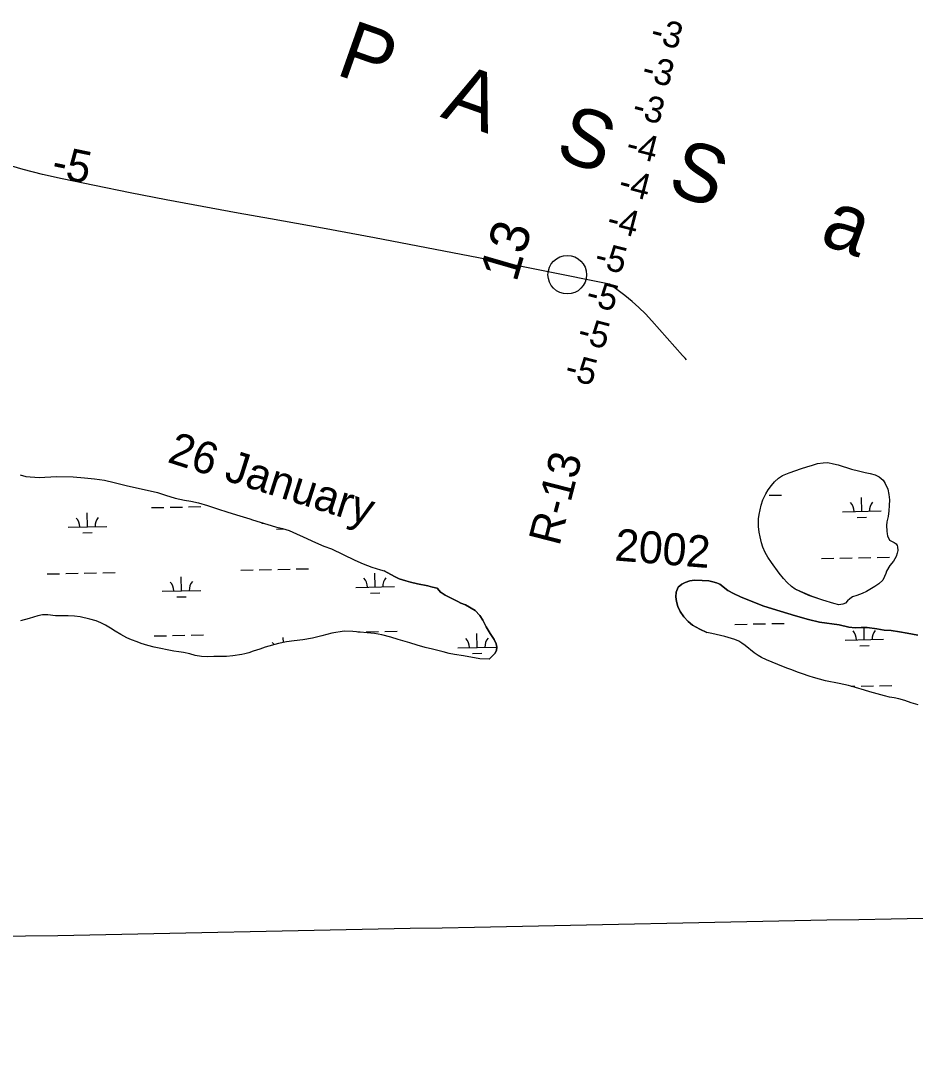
# Model space of a CAD drawing. Extents: x 3989314 to 4027622, y 243956 to 270014.
# Drawn here: x 4009687 to 4012006, y 255456 to 258147 of the extents above; entities that cross this region are included whole.
import ezdxf

# ---------------------------------------------------------------- set-up
doc = ezdxf.new("R2010")
doc.units = 0
for name, color, linetype in [('V-GRID-MAJR', 7, 'Continuous'), ('V-RIVR-EDGE', 7, 'Continuous'), ('V-RIVR-IDEN', 7, 'Continuous'), ('V-RIVR-MILE', 7, 'Continuous'), ('V-RIVR-RANG', 7, 'Continuous'), ('V-RIVR-RANG-IDEN', 7, 'Continuous'), ('V-TOPO-MINR', 7, 'Continuous'), ('V-TOPO-MINR-IDEN', 7, 'Continuous'), ('V-WETL-SWMP', 7, 'Continuous')]:
    doc.layers.add(name, color=color, linetype=linetype)

msp = doc.modelspace()

# ---------------------------------------------------------------- linework, layer by layer
at = {"layer": 'V-GRID-MAJR'}
msp.add_spline([(3993497.6, 255455.7), (3998815.3, 255559.8), (4004133, 255664.6), (4009450.7, 255770.2), (4014768.4, 255876.5), (4020086, 255983.7), (4025403.7, 256091.6)], degree=3, dxfattribs=at)
at = {"layer": 'V-RIVR-EDGE'}
for points in [[(4011730.5, 256658), (4011694.9, 256674.5), (4011685.5, 256680.7), (4011674.4, 256691.6), (4011664.7, 256702), (4011653, 256715.7), (4011633.4, 256743.1), (4011623.8, 256757.3), (4011617.3, 256769), (4011611.3, 256782.7), (4011607.4, 256794), (4011603.9, 256810), (4011601.6, 256821.8), (4011599.8, 256836.8), (4011599.9, 256856.5), (4011601.4, 256868), (4011606.3, 256892.2), (4011611, 256905.6), (4011618.6, 256921), (4011625.2, 256931.6), (4011633.3, 256942.7), (4011641.1, 256952.1), (4011651.5, 256961.5), (4011662.1, 256969.2), (4011679.4, 256975.7), (4011711.6, 256987), (4011725.1, 256991.5), (4011739.9, 256995.6), (4011752.6, 256999.5), (4011767.4, 257001.7), (4011779.9, 257002.1), (4011794.4, 256999.4), (4011805.9, 256996.1), (4011840.6, 256985.2), (4011858.8, 256980.5), (4011876.5, 256976.3), (4011889.1, 256973.7), (4011902.6, 256970.2), (4011912.4, 256965.5), (4011922.9, 256956.3), (4011928.1, 256948.2), (4011934.7, 256933.7), (4011938.1, 256919.4), (4011939.3, 256905.9), (4011938.7, 256890.9), (4011937.9, 256876.8), (4011936, 256862.5), (4011932.4, 256849.1), (4011931.4, 256839.1), (4011932.2, 256824.4), (4011933.4, 256817.4), (4011934.4, 256812.8), (4011939.7, 256801.3), (4011951.9, 256795.2), (4011956.4, 256791.6), (4011959.3, 256787.4), (4011959.8, 256784), (4011960.7, 256774.6), (4011959.7, 256767.5), (4011956.5, 256758.4), (4011950, 256746.6), (4011940.1, 256735.1), (4011931.8, 256720.4), (4011929.8, 256714.5), (4011926.6, 256706.6), (4011921.8, 256697.9), (4011911.4, 256688.1), (4011901.3, 256681.4), (4011879.4, 256668), (4011868.7, 256662.9), (4011855, 256657.9), (4011843.8, 256654.2), (4011836.9, 256649), (4011830.9, 256643.8), (4011825, 256638.2), (4011818.8, 256635.5), (4011808, 256633.8), (4011795.1, 256636.8), (4011767, 256645.7), (4011730.5, 256658)], [(4009685.5, 256970.4), (4009700.4, 256966.3), (4009734.9, 256963.5), (4009780.2, 256966.6), (4009823.2, 256965.5), (4009852.6, 256963), (4009878.7, 256960.4), (4009904.2, 256956.3), (4009929.4, 256950.8), (4009960.4, 256942.7), (4010042.1, 256924.3), (4010062.8, 256918), (4010087.2, 256910.1), (4010111.5, 256904.8), (4010128.1, 256902.5), (4010148.1, 256897.8), (4010171.3, 256890.7), (4010199.8, 256881.2), (4010221.9, 256874.6), (4010246.8, 256866.6), (4010280.9, 256856.6), (4010288.3, 256853.9), (4010327.9, 256841.5), (4010347.3, 256835.7), (4010365.8, 256831.3), (4010383.4, 256826), (4010402.5, 256818), (4010419.2, 256809.6), (4010451.7, 256794.7), (4010472.7, 256785.9), (4010492.8, 256778.6), (4010553, 256749.2), (4010575, 256740.1), (4010597.7, 256731.6), (4010620, 256724.4), (4010629.5, 256722)], [(4010766.6, 256677.1), (4010755.1, 256679.4), (4010742.2, 256682.4), (4010715.5, 256688.1), (4010697.5, 256692.7), (4010685.4, 256696), (4010668, 256701.3), (4010656, 256706.6), (4010629.5, 256722)], [(4011433.9, 256697.2), (4011421.5, 256695.7), (4011409.6, 256691.3), (4011400.7, 256687.3), (4011391.7, 256679), (4011386.4, 256666.8), (4011385.5, 256654.3), (4011387, 256642.1), (4011390.6, 256629.2), (4011397, 256616.5), (4011406.2, 256602.3), (4011417.5, 256590.4), (4011429, 256580.8), (4011447.6, 256570.7), (4011465.7, 256562.1)], [(4012012.7, 256555.3), (4011985.2, 256560.4), (4011965.5, 256563.8), (4011944.1, 256566.6), (4011926, 256567.8), (4011906.2, 256570.9), (4011881.9, 256574.5), (4011865.9, 256574.4), (4011850.4, 256573.6), (4011833.8, 256575.3), (4011808.6, 256581.5), (4011757.5, 256588.7), (4011729.6, 256595.5), (4011695.8, 256604.8), (4011636.3, 256623.1), (4011611.4, 256631.3), (4011553, 256654.1), (4011534.6, 256662.8), (4011520.5, 256670.5), (4011499.9, 256686.7), (4011491.3, 256690.6), (4011481.2, 256693.5), (4011470.7, 256695.5), (4011454, 256696.9), (4011433.9, 256697.2)], [(4010820.1, 256642.1), (4010798.1, 256653.1), (4010787.5, 256658.5), (4010777.3, 256665.2), (4010776.7, 256665.9), (4010766.6, 256677.1)], [(4010901.9, 256492.8), (4010917.1, 256508), (4010920.5, 256516.4), (4010921.3, 256524.2), (4010919.3, 256532.4), (4010914.2, 256543.5), (4010904.5, 256558.9), (4010894, 256576.5), (4010885.3, 256593.9), (4010877.4, 256605.8), (4010865.6, 256618.5), (4010840.1, 256633.7), (4010828.5, 256638.2), (4010820.1, 256642.1)], [(4010901.9, 256492.8), (4010877.4, 256493.8), (4010835.3, 256501.7), (4010811.4, 256504.9), (4010798.2, 256507.7), (4010782, 256511.9), (4010755.1, 256518.4), (4010735.6, 256522.9), (4010714.5, 256529.1), (4010695.9, 256534.9), (4010665.9, 256543.7), (4010646.3, 256549.9), (4010623.6, 256556), (4010604.4, 256559.5), (4010547.9, 256564.6), (4010525.3, 256565.7), (4010493.5, 256559.8), (4010467.8, 256552.8), (4010443.6, 256547.5), (4010418.1, 256543), (4010396, 256540.6), (4010376.6, 256537.9), (4010355.2, 256533.3), (4010321.3, 256523.4), (4010306.8, 256518.2), (4010290.2, 256513.1), (4010278.2, 256509.1), (4010268.5, 256506.4), (4010260.8, 256505), (4010237.2, 256501), (4010220.6, 256499.5), (4010204.5, 256499.4), (4010187.8, 256499.6), (4010171.5, 256499.1), (4010156, 256499.3), (4010139.5, 256502.4), (4010125.9, 256506.1), (4010109.1, 256510.1), (4010096.8, 256511.9), (4010084.2, 256513.3), (4010032.8, 256524.2), (4010016.4, 256528), (4009999.6, 256533.3), (4009988.7, 256537.2), (4009974.1, 256542.9), (4009961.9, 256548.3), (4009947, 256556.4), (4009931.7, 256565.4), (4009920, 256572.7), (4009907, 256580.5), (4009894.9, 256586.9), (4009882.6, 256591.9), (4009866.6, 256596.8), (4009841.5, 256602.5), (4009826.3, 256604.4), (4009810.1, 256604.7), (4009794.4, 256604.7), (4009777.6, 256605.1), (4009757.3, 256607.2), (4009743.4, 256607.5), (4009731.2, 256604.9), (4009708.7, 256597.8), (4009686.2, 256592.1)], [(4011607.6, 256496.9), (4011599, 256502.1), (4011588.3, 256509.3), (4011564.9, 256528.5), (4011557, 256534.4), (4011548.9, 256539.4), (4011538.8, 256543.4), (4011512.3, 256551.8), (4011478.9, 256558.9), (4011465.7, 256562.1)], [(4012013.3, 256374.2), (4011995.7, 256379.8), (4011978.8, 256385.5), (4011963.7, 256389.7), (4011951.8, 256392.3), (4011939.5, 256394.3), (4011926.2, 256397.7), (4011888.4, 256408), (4011874.8, 256412.2), (4011851.4, 256419.2), (4011833.2, 256424.1), (4011808.7, 256429.6), (4011773.9, 256436.6), (4011758.3, 256440.7), (4011742.7, 256445.3), (4011731, 256449), (4011713.8, 256455), (4011700.8, 256459.2), (4011685.8, 256464.7), (4011673.3, 256469.7), (4011649.6, 256478.7), (4011620.3, 256490.6), (4011607.6, 256496.9)]]:
    msp.add_lwpolyline(points, dxfattribs=at)
at = {"layer": 'V-RIVR-MILE'}
msp.add_circle((4011104, 257489.3), 50, dxfattribs=at)
at = {"layer": 'V-TOPO-MINR'}
msp.add_lwpolyline([(4011412.9, 257268.8), (4011409.7, 257272.6), (4011406.4, 257276.4), (4011403.1, 257280.2), (4011323.4, 257370.1), (4011307, 257387.5), (4011289.9, 257404.2), (4011271.9, 257420), (4011253.3, 257435), (4011215.5, 257463.7), (4011215.3, 257463.8), (4011214.5, 257464.3), (4011213.3, 257464.7), (4010874.2, 257532.7), (4010739.5, 257559.2), (4010604.7, 257585.1), (4010469.7, 257610), (4010334.5, 257634.3), (4010251.1, 257649), (4010157.7, 257665.9), (4010064.4, 257683.4), (4009971.3, 257701.7), (4009878.3, 257720.5), (4009794.9, 257737.9), (4009743.9, 257749.4), (4009693.2, 257762.2), (4009643, 257776.8)], dxfattribs=at)
at = {"layer": 'V-WETL-SWMP'}
for p, q in [((4011627.7, 256917.4), (4011659.7, 256918.1)), ((4011867.4, 256875.8), (4011866.7, 256911.8)), ((4010026.3, 256885.5), (4010058.3, 256886.2)), ((4010074.3, 256886.5), (4010106.3, 256887.1)), ((4010122.3, 256887.4), (4010154.3, 256888.1)), ((4011817.4, 256874.8), (4011917.4, 256876.8)), ((4009860.2, 256835.8), (4009859.5, 256871.8)), ((4011855.7, 256860.1), (4011879.7, 256860.6)), ((4009810.2, 256834.8), (4009910.2, 256836.8)), ((4009848.5, 256820.1), (4009872.5, 256820.6)), ((4010312, 256844.8), (4010317.2, 256844.9)), ((4010350.3, 256830.1), (4010368.7, 256830.5)), ((4011763, 256753.6), (4011795, 256754.2)), ((4011811, 256754.5), (4011843, 256755.2)), ((4011859, 256755.5), (4011891, 256756.1)), ((4011907, 256756.5), (4011939, 256757.1)), ((4009755.8, 256713.6), (4009787.8, 256714.2)), ((4009803.8, 256714.5), (4009835.8, 256715.2)), ((4009851.8, 256715.5), (4009883.7, 256716.1)), ((4009899.7, 256716.5), (4009931.7, 256717.1)), ((4010257.6, 256723.6), (4010289.6, 256724.2)), ((4010305.6, 256724.5), (4010337.6, 256725.2)), ((4010353.6, 256725.5), (4010385.6, 256726.1)), ((4010401.6, 256726.5), (4010433.5, 256727.1)), ((4010605.8, 256679.8), (4010605.1, 256715.8)), ((4010104, 256669.8), (4010103.3, 256705.8)), ((4010054, 256668.8), (4010154, 256670.8)), ((4010555.8, 256678.8), (4010655.8, 256680.8)), ((4010594.1, 256664.1), (4010618.1, 256664.6)), ((4010092.3, 256654.1), (4010116.3, 256654.6)), ((4011538.4, 256582.9), (4011570.4, 256583.5)), ((4011586.4, 256583.9), (4011618.3, 256584.5)), ((4011634.3, 256584.8), (4011666.3, 256585.5)), ((4010032.9, 256552.9), (4010064.9, 256553.5)), ((4010080.9, 256553.9), (4010112.9, 256554.5)), ((4010128.9, 256554.8), (4010160.9, 256555.5)), ((4010561.2, 256563.4), (4010566.7, 256563.5)), ((4010582.7, 256563.9), (4010614.7, 256564.5)), ((4010630.7, 256564.8), (4010662.7, 256565.5)), ((4010870.4, 256523.2), (4010869.7, 256559.1)), ((4011874.1, 256543.2), (4011873.4, 256574.5)), ((4010368.2, 256536.1), (4010367.9, 256549.1)), ((4010820.5, 256522.2), (4010920.4, 256524.2)), ((4011824.1, 256542.2), (4011924.1, 256544.2)), ((4011862.4, 256527.5), (4011886.4, 256528)), ((4010858.8, 256507.5), (4010882.8, 256508)), ((4011839.6, 256422.4), (4011849.6, 256422.6)), ((4011865.6, 256422.9), (4011897.6, 256423.5)), ((4011913.6, 256423.9), (4011945.6, 256424.5))]:
    msp.add_line(p, q, dxfattribs=at)
msp.add_lwpolyline([(4011603.9, 256810), (4011601.6, 256821.8), (4011599.8, 256836.8), (4011599.9, 256856.5), (4011601.4, 256868), (4011606.3, 256892.2), (4011611, 256905.6), (4011618.6, 256921), (4011625.2, 256931.6), (4011633.3, 256942.7), (4011641.1, 256952.1), (4011651.5, 256961.5), (4011662.1, 256969.2), (4011679.4, 256975.7), (4011711.6, 256987), (4011725.1, 256991.5), (4011739.9, 256995.6), (4011752.6, 256999.5), (4011767.4, 257001.7), (4011779.9, 257002.1), (4011794.4, 256999.4), (4011805.9, 256996.1), (4011840.6, 256985.2), (4011858.8, 256980.5), (4011876.5, 256976.3), (4011889.1, 256973.7), (4011902.6, 256970.2), (4011912.4, 256965.5), (4011922.9, 256956.3), (4011928.1, 256948.2), (4011934.7, 256933.7), (4011938.1, 256919.4), (4011939.3, 256905.9), (4011938.7, 256890.9), (4011937.9, 256876.8), (4011936, 256862.5), (4011932.4, 256849.1), (4011931.4, 256839.1), (4011932.2, 256824.4), (4011933.4, 256817.4), (4011934.4, 256812.8), (4011939.7, 256801.3), (4011951.9, 256795.2), (4011956.4, 256791.6), (4011959.3, 256787.4), (4011959.8, 256784), (4011960.7, 256774.6), (4011959.7, 256767.5), (4011956.5, 256758.4), (4011950, 256746.6), (4011940.1, 256735.1), (4011931.8, 256720.4), (4011929.8, 256714.5), (4011926.6, 256706.6), (4011921.8, 256697.9), (4011911.4, 256688.1), (4011901.3, 256681.4), (4011879.4, 256668), (4011868.7, 256662.9), (4011855, 256657.9), (4011843.8, 256654.2), (4011836.9, 256649), (4011830.9, 256643.8), (4011825, 256638.2), (4011818.8, 256635.5), (4011808, 256633.8), (4011795.1, 256636.8), (4011767, 256645.7), (4011738.8, 256655.2), (4011726.4, 256659.9), (4011694.9, 256674.5), (4011685.5, 256680.7), (4011674.4, 256691.6), (4011664.7, 256702), (4011653, 256715.7), (4011633.4, 256743.1), (4011623.8, 256757.3), (4011617.3, 256769), (4011611.3, 256782.7), (4011607.4, 256794)], close=True, dxfattribs=at)
for points in [[(4009685.5, 256970.4), (4009700.4, 256966.3), (4009734.9, 256963.5), (4009780.2, 256966.6), (4009823.2, 256965.5), (4009852.6, 256963), (4009878.7, 256960.4), (4009904.2, 256956.3), (4009929.4, 256950.8), (4009960.4, 256942.7), (4010042.1, 256924.3), (4010062.8, 256918), (4010087.2, 256910.1), (4010111.5, 256904.8), (4010128.1, 256902.5), (4010148.1, 256897.8), (4010171.3, 256890.7), (4010199.8, 256881.2), (4010221.9, 256874.6), (4010246.8, 256866.6), (4010280.9, 256856.6), (4010288.3, 256853.9), (4010327.9, 256841.5), (4010347.3, 256835.7), (4010365.8, 256831.3), (4010383.4, 256826), (4010402.5, 256818), (4010419.2, 256809.6), (4010451.7, 256794.7), (4010472.7, 256785.9), (4010492.8, 256778.6), (4010553, 256749.2), (4010575, 256740.1), (4010597.7, 256731.6), (4010620, 256724.4), (4010629.5, 256722), (4010656, 256706.6), (4010668, 256701.3), (4010685.4, 256696), (4010697.5, 256692.7), (4010715.5, 256688.1), (4010742.2, 256682.4), (4010755.1, 256679.4), (4010766.6, 256677.1), (4010776.7, 256665.9), (4010777.3, 256665.2), (4010787.5, 256658.5), (4010798.1, 256653.1), (4010820.1, 256642.1), (4010828.5, 256638.2), (4010840.1, 256633.7), (4010865.6, 256618.5), (4010877.4, 256605.8), (4010885.3, 256593.9), (4010894, 256576.5), (4010904.5, 256558.9), (4010914.2, 256543.5), (4010919.3, 256532.4), (4010921.3, 256524.2), (4010920.5, 256516.4), (4010917.1, 256508), (4010901.9, 256492.8), (4010877.4, 256493.8), (4010835.3, 256501.7), (4010811.4, 256504.9), (4010798.2, 256507.7), (4010782, 256511.9), (4010755.1, 256518.4), (4010735.6, 256522.9), (4010714.5, 256529.1), (4010695.9, 256534.9), (4010665.9, 256543.7), (4010646.3, 256549.9), (4010623.6, 256556), (4010604.4, 256559.5), (4010547.9, 256564.6), (4010525.3, 256565.7), (4010493.5, 256559.8), (4010467.8, 256552.8)], [(4012013.3, 256374.2), (4011995.7, 256379.8), (4011978.8, 256385.5), (4011963.7, 256389.7), (4011951.8, 256392.3), (4011939.5, 256394.3), (4011926.2, 256397.7), (4011888.4, 256408), (4011874.8, 256412.2), (4011851.4, 256419.2), (4011833.2, 256424.1), (4011808.7, 256429.6), (4011773.9, 256436.6), (4011758.3, 256440.7), (4011742.7, 256445.3), (4011731, 256449), (4011713.8, 256455), (4011700.8, 256459.2), (4011685.8, 256464.7), (4011673.3, 256469.7), (4011649.6, 256478.7), (4011620.3, 256490.6), (4011607.6, 256496.9), (4011599, 256502.1), (4011588.3, 256509.3), (4011564.9, 256528.5), (4011557, 256534.4), (4011548.9, 256539.4), (4011538.8, 256543.4), (4011512.3, 256551.8), (4011478.9, 256558.9), (4011465.7, 256562.1), (4011447.6, 256570.7), (4011429, 256580.8), (4011417.5, 256590.4), (4011406.2, 256602.3), (4011397, 256616.5), (4011390.6, 256629.2), (4011387, 256642.1), (4011385.5, 256654.2), (4011386.4, 256666.8), (4011391.7, 256679), (4011400.7, 256687.3), (4011409.6, 256691.3), (4011421.5, 256695.7), (4011433.9, 256697.2)], [(4011433.9, 256697.2), (4011454, 256696.9), (4011470.7, 256695.5), (4011481.2, 256693.5), (4011491.3, 256690.6), (4011499.9, 256686.7), (4011520.5, 256670.5), (4011534.6, 256662.8), (4011553, 256654.1), (4011611.4, 256631.3), (4011636.3, 256623.1), (4011695.8, 256604.8), (4011729.6, 256595.5), (4011757.5, 256588.7), (4011808.6, 256581.5), (4011833.8, 256575.3), (4011850.4, 256573.6), (4011865.9, 256574.4), (4011881.9, 256574.5), (4011906.2, 256570.9), (4011926, 256567.8), (4011944.1, 256566.6), (4011965.5, 256563.8), (4011985.2, 256560.4), (4012012.7, 256555.3)], [(4010467.8, 256552.8), (4010443.6, 256547.5), (4010418.1, 256543), (4010396, 256540.6), (4010376.6, 256537.9), (4010355.2, 256533.3), (4010321.3, 256523.4), (4010306.8, 256518.2), (4010290.2, 256513.1), (4010278.2, 256509.1), (4010268.5, 256506.4), (4010260.8, 256505), (4010237.2, 256501), (4010220.6, 256499.5), (4010204.5, 256499.4), (4010187.8, 256499.6), (4010171.5, 256499.1), (4010156, 256499.3), (4010139.5, 256502.4), (4010125.9, 256506.1), (4010109.1, 256510.1), (4010096.8, 256511.9), (4010084.2, 256513.3), (4010032.8, 256524.2), (4010016.4, 256528), (4009999.6, 256533.3), (4009988.7, 256537.2), (4009974.1, 256542.9), (4009961.9, 256548.3), (4009947, 256556.4), (4009931.7, 256565.4), (4009920, 256572.7), (4009907, 256580.5), (4009894.9, 256586.9), (4009882.6, 256591.9), (4009866.6, 256596.8), (4009841.5, 256602.5), (4009826.3, 256604.4), (4009810.1, 256604.7), (4009794.4, 256604.7), (4009777.6, 256605.1), (4009757.3, 256607.2), (4009743.4, 256607.5), (4009731.2, 256604.9), (4009708.7, 256597.8), (4009686.2, 256592.1)]]:
    msp.add_lwpolyline(points, dxfattribs=at)
for centre, start, end in [((4011812.2, 256875.1), 0.3699, 41.9135), ((4011922.7, 256877.3), 140.3699, 181.9135), ((4009805, 256835.1), 0.3699, 41.9135), ((4009915.4, 256837.3), 140.3699, 181.9135), ((4010048.8, 256669.2), 0.3699, 41.9135), ((4010159.3, 256671.4), 140.3699, 181.9135), ((4010550.6, 256679.2), 0.3699, 41.9135), ((4010661.1, 256681.4), 140.3699, 181.9135), ((4011818.8, 256542.5), 0.3699, 41.9135), ((4011929.3, 256544.7), 140.3699, 181.9135), ((4010313.4, 256512.5), 29.7445, 41.9135), ((4010815.2, 256522.5), 0.3699, 41.9135), ((4010925.7, 256524.7), 140.3699, 181.9135)]:
    msp.add_arc(centre, 35.2, start, end, dxfattribs=at)

# ---------------------------------------------------------------- texts
at = {"layer": 'V-RIVR-IDEN'}
for s, height, rotation, p in [('P', 150, 340.524, (4010500.4, 258009.5)), ('A', 150, 340.524, (4010772.7, 257899)), ('S', 150, 340.524, (4011068, 257794)), ('S', 150, 340.524, (4011358.9, 257704.9)), ('a', 150, 340.524, (4011754.6, 257571)), ('13', 100, 73.8891, (4010972, 257467.3)), ('26 January', 83, 342.3874, (4010064.7, 257004.4)), ('2002', 83, 355.3645, (4011225.1, 256748.7))]:
    msp.add_text(s, height=height, rotation=rotation, dxfattribs=at).set_placement(p)
at = {"layer": 'V-RIVR-RANG'}
for s, p in [('-3', (4011316.4, 258093.1)), ('-3', (4011294, 257995.6)), ('-3', (4011269.4, 257898.5)), ('-4', (4011252.6, 257799.6)), ('-4', (4011233.3, 257701.5)), ('-4', (4011202.9, 257605.8)), ('-5', (4011171.4, 257510.8)), ('-5', (4011149.1, 257413.3)), ('-5', (4011127.3, 257315.6)), ('-5', (4011094.4, 257220.8))]:
    msp.add_text(s, height=67, rotation=345.585, dxfattribs=at).set_placement(p)
at = {"layer": 'V-RIVR-RANG-IDEN'}
msp.add_text('R-13 ', height=83, rotation=75.5958, dxfattribs=at).set_placement((4011083.3, 256783.6))
at = {"layer": 'V-TOPO-MINR-IDEN'}
msp.add_text('-5', height=83, rotation=348.2673, dxfattribs=at).set_placement((4009763.8, 257744.3))

doc.saveas('drawing.dxf')
